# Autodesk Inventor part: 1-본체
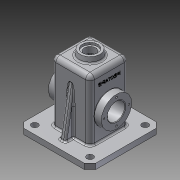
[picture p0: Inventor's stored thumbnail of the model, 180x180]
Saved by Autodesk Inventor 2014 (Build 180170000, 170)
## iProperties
Created: 2016-02
Part Number: 1-본체
Material: 알루미늄 6061
Document SubType Name: Modeling
Designer: Administrator
Density: 2.71 g/cm^3
Appearance: 알루미늄 - 평지
Mass: 932.811 g
Surface Area: 1043.48 cm^2
Volume: 344.211 cm^3
Author: Administrator
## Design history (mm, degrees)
sketch "스케치1"
  geometry: L1 (-65, 0)-(65, 0); L2 (65, 0)-(65, 10); L3 (65, 10)-(-65, 10); L4 (-65, 10)-(-65, 0); L5 (-35, 10)-(35, 10); L6 (35, 10)-(35, 120); L7 (35, 120)-(-35, 120); L8 (-35, 120)-(-35, 10); 3 further points
  constraints: 16 end point, 4 parallel, 3 midpoint, 2 horizontal, 2 perpendicular, 1 coincident
  dimensions: "d0" = 10 distance of L1.end L2.end; "d1" = 130 distance of L2.end L3.end; "d2" = 70 distance of L6.end L7.end; "d3" = 120 distance between parallel lines of L1 L7
extrude "돌출1" new body sketch "스케치1" stored distance "d4" = 70; taper "d5" = 0 deg
extrude "돌출2" join sketch "스케치1" stored distance "d6" = 130; taper "d7" = 0 deg
sketch "스케치4"
  geometry: L1 (0, -65)-(0, 65) reference; C1 r 27.5 at (-55, 0); 2 further points
  constraints: 1 centre point, 1 horizontal alignment, 1 midpoint
  dimensions: "d15" = 55 diameter of C1; "d16" = 55 distance from line of C1.centre L1
extrude "돌출5" join sketch "스케치4" distance "d17" = 13; taper "d18" = 0 deg
sketch "스케치5"
  geometry: L1 (-50, 10)-(-30.604, 120); L2 (-30.604, 120)-(30.604, 120); L3 (30.604, 120)-(50, 10); L4 (50, 10)-(-50, 10); L5 (35, 10)-(65, 10) reference; L6 (65, 10)-(65, 0) reference; L7 (65, 0)-(-65, 0) reference; L8 (-65, 0)-(-65, 10) reference; L9 (-65, 10)-(-35, 10) reference; L10 (-35, 10)-(-35, 120) reference; L11 (-35, 120)-(35, 120) reference; L12 (35, 120)-(35, 10) reference; 1 further point
  constraints: 8 end point, 2 collinear, 1 horizontal, 1 parallel
  dimensions: "d19" = 80 deg angle of L4 L1; "d20" = 80 deg angle of L4 L3; "d21" = 15 horizontal distance of L1.start L7.end; "d22" = 15 distance of L5.end L3.end
extrude "돌출6" join sketch "스케치5" stored distance "d23" = 10; taper "d24" = 0 deg
sketch "스케치2"
  geometry: L1 (95, -95)-(35, -95); L2 (35, -95)-(35, -35); L3 (35, -35)-(95, -35); L4 (95, -35)-(95, -95); 3 further points
  constraints: 8 end point, 2 midpoint, 2 parallel, 1 horizontal, 1 horizontal alignment, 1 perpendicular, 1 vertical alignment
  dimensions: "d8" = 60 distance of L1.start L1.end; "d9" = 60 distance of L1.end L2.end
extrude "돌출3" cut sketch "스케치2" distance "d10" = 115; taper "d11" = 0 deg
sketch "스케치3"
  geometry: C1 r 20 at (35, 35); 1 further point
  constraints: 1 centre point, 1 coincident
  dimensions: "d12" = 40 diameter of C1
extrude "돌출4" join sketch "스케치3" distance "d13" = 10; taper "d14" = -10 deg
sketch "스케치6"
  geometry: L1 (-35, 27.5)-(-48, 27.5) reference; L2 (-48, 27.5)-(-48, 82.5) reference; L3 (-48, 82.5)-(-35, 82.5) reference; L4 (-35, 82.5)-(-35, 120) reference; L5 (-35, 120)-(-20, 120) reference; L6 (-20, 120)-(-18.237, 130) reference; L7 (-18.237, 130)-(18.237, 130) reference; L8 (18.237, 130)-(20, 120) reference; L9 (20, 120)-(35, 120) reference; L10 (35, 120)-(35, 10) reference; L11 (35, 10)-(65, 10) reference; L12 (65, 10)-(65, 0) reference; L13 (65, 0)-(30, 0) reference; L14 (30, 0)-(30, 115) reference; L15 (30, 115)-(-30, 115) reference; L16 (-30, 115)-(-30, 0) reference; L17 (-30, 0)-(-65, 0) reference; L18 (-65, 0)-(-65, 10) reference; L19 (-65, 10)-(-35, 10) reference; L20 (-35, 10)-(-35, 27.5) reference; L21 (-30, 82.5)-(-23, 75.5); L22 (-23, 75.5)-(-23, 34.5); L23 (-23, 34.5)-(-30, 27.5); L24 (-30, 27.5)-(-30, 82.5); L25 (-23, 55)-(-30, 55); 1 further point
  constraints: 10 end point, 2 midpoint, 2 parallel, 1 collinear, 1 perpendicular
  dimensions: "d25" = 55 distance between parallel lines of L25 L17; "d26" = 7 distance between parallel lines of L16 L22; "d27" = 55 distance of L23.end L21.start; "d28" = 135 deg angle of L16 L23; "d29" = 135 deg angle of L16 L21
revolve "회전1" sketch "스케치6" stored, may be unused: angle "d30" = 90 deg
hole "구멍1" diameter "d33" = 32; stored, may be unused: countersink angle "d37" = 90 deg, drill point angle "d39" = 118 deg; dims "d31" = 10, "d32" = 10, "d34" = 6, "d35" = 4, "d36" = 2, "d38" = 8
sketch "스케치7"
  geometry: L1 (0, 0)-(-22.5, 0); C1 r 16 at (0, 0) reference; 1 further point
  constraints: 2 end point, 1 horizontal
  dimensions: "d40" = 22.5 distance of L1.start L1.end
hole "구멍2" sketch "스케치7" at (-22.5, 0) diameter "d41" = 3.242; stored, may be unused: countersink angle "d45" = 90 deg, drill point angle "d47" = 118 deg; dims "d42" = 8, "d43" = 4, "d44" = 2, "d46" = 10
chamfer "모따기1" distance "d51" = 1; stored, may be unused: second distance "d52" = 2, angle "d53" = 45 deg
fillet "모깎기1" dims "d54" = 0.5
fillet "모깎기2" dims "d55" = 3
fillet "모깎기3" dims "d56" = 3
fillet "모깎기6" dims "d59" = 3
fillet "모깎기7" dims "d60" = 3
fillet "모깎기11" dims "d64" = 8
fillet "모깎기12" dims "d65" = 8
fillet "모깎기13" dims "d66" = 0.5
fillet "모깎기14" dims "d67" = 0.5
fillet "모깎기15" dims "d68" = 3
chamfer "모따기2" distance "d69" = 10; stored, may be unused: second distance "d70" = 2, angle "d71" = 45 deg
sketch "스케치8"
  geometry: L1 (0, 0)-(110, 0) reference; L2 (-10, 10)-(-10, 120) reference; 2 further points
  dimensions: "d72" = 15 distance from line of point (5, 15) L1; "d73" = 15 distance from line of L2 point (5, 15)
hole "구멍3" sketch "스케치8" at (5, 15) diameter "d74" = 12; stored, may be unused: countersink angle "d78" = 90 deg, drill point angle "d80" = 0 deg; dims "d75" = 8, "d76" = 4, "d77" = 2, "d79" = 10
hole "구멍4" diameter "d83" = 21; stored, may be unused: countersink angle "d87" = 90 deg, drill point angle "d89" = 0 deg; dims "d81" = 10, "d82" = 10, "d84" = 8, "d85" = 28, "d86" = 4, "d88" = 10
sketch "스케치9"
  geometry: L1 (-70, -35)-(-70, 35); L2 (-70, 35)-(-130, 35); L3 (-130, 35)-(-130, -35); L4 (-130, -35)-(-70, -35); L5 (-13, 35)-(-112, 35) reference; L6 (-130, -18.237)-(-130, 18.237) reference; 5 further points
  constraints: 4 midpoint, 1 coincident, 1 collinear, 2 other
  dimensions: "d90" = 35 distance from line of L5 point (-70, 0); "d91" = 30 distance from line of point (-100, 35) L6
feature "엠보싱1" sketch "스케치9" dims "d0" = 10, "d1" = 130, "d2" = 70, "d3" = 120, "d92" = 0.5, "d93" = 0
fillet "모깎기16" dims "d94" = 3
node "솔리드1"
pattern_circular "원형 패턴1" dims angle "d49" = 360 deg
mirror "대칭1"
mirror "대칭2"
mirror "대칭3"
node "절단 모서리 투영1"
node "절단 모서리 투영2"
